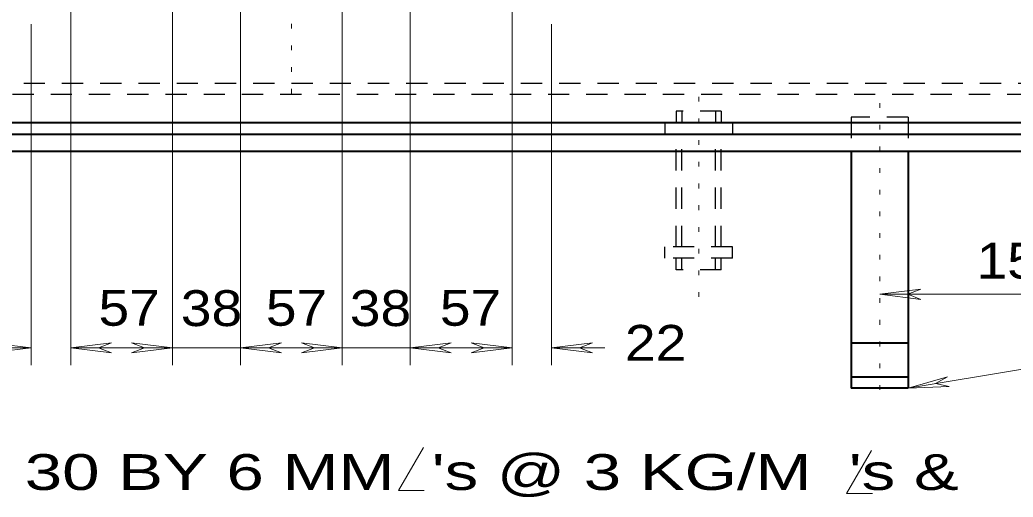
# Model space of a CAD drawing. Extents: x 312583 to 312854, y 144419 to 144597.
# Drawn here: x 312664.38 to 312685.41, y 144537.74 to 144547.86 of the extents above; entities that cross this region are included whole.
import ezdxf

# ---------------------------------------------------------------- set-up
doc = ezdxf.new("R2010")
doc.units = 0
doc.header["$LTSCALE"] = 0.3
doc.linetypes.add('DOTTED', pattern=[1.5, 0.3, -1.2])
doc.linetypes.add('SHORT_DASHED', pattern=[2.7, 1.5, -1.2])
doc.layers.add('1', color=7, linetype='Continuous', lineweight=13)

msp = doc.modelspace()

# ---------------------------------------------------------------- linework, layer by layer
at = {"layer": '1'}
for p, q in [((312665.4586, 144554.099), (312665.4586, 144540.5366)), ((312667.6129, 144554.007), (312667.6129, 144540.5366)), ((312674.8043, 144553.6926), (312674.8043, 144540.5366)), ((312669.0543, 144553.4013), (312669.0543, 144540.5366)), ((312671.2086, 144553.4013), (312671.2086, 144540.5366)), ((312672.6499, 144553.4243), (312672.6499, 144540.5366)), ((312664.6229, 144547.7663), (312664.6229, 144540.5366)), ((312675.6399, 144547.7663), (312675.6399, 144540.5366)), ((312682.5936, 144542.0393), (312683.4599, 144542.1466)), ((312688.5813, 144542.0393), (312682.5936, 144542.0393)), ((312682.5936, 144542.0393), (312683.4599, 144541.932)), ((312683.4599, 144542.1466), (312683.1839, 144542.0393)), ((312683.4599, 144541.932), (312683.1839, 144542.0393)), ((312664.6229, 144540.9046), (312663.7566, 144541.012)), ((312665.4586, 144540.9046), (312666.3249, 144541.012)), ((312666.3249, 144541.012), (312666.0489, 144540.9046)), ((312666.7466, 144541.012), (312667.0226, 144540.9046)), ((312667.6129, 144540.9046), (312666.7466, 144541.012)), ((312669.0543, 144540.9046), (312669.9206, 144541.012)), ((312669.9206, 144541.012), (312669.6446, 144540.9046)), ((312670.3423, 144541.012), (312670.6183, 144540.9046)), ((312671.2086, 144540.9046), (312670.3423, 144541.012)), ((312672.6499, 144540.9046), (312673.5163, 144541.012)), ((312673.5163, 144541.012), (312673.2403, 144540.9046)), ((312673.9379, 144541.012), (312674.2139, 144540.9046)), ((312674.8043, 144540.9046), (312673.9379, 144541.012)), ((312675.6399, 144540.9046), (312676.5063, 144541.012)), ((312676.5063, 144541.012), (312676.2303, 144540.9046)), ((312663.3809, 144540.9046), (312664.6229, 144540.9046)), ((312664.6229, 144540.9046), (312663.7566, 144540.7973)), ((312665.4586, 144540.9046), (312666.3249, 144540.7973)), ((312666.3249, 144540.7973), (312666.0489, 144540.9046)), ((312666.7466, 144540.7973), (312667.0226, 144540.9046)), ((312667.6129, 144540.9046), (312666.7466, 144540.7973)), ((312669.0543, 144540.9046), (312669.9206, 144540.7973)), ((312669.9206, 144540.7973), (312669.6446, 144540.9046)), ((312670.3423, 144540.7973), (312670.6183, 144540.9046)), ((312671.2086, 144540.9046), (312670.3423, 144540.7973)), ((312672.6499, 144540.9046), (312673.5163, 144540.7973)), ((312673.5163, 144540.7973), (312673.2403, 144540.9046)), ((312673.9379, 144540.7973), (312674.2139, 144540.9046)), ((312674.8043, 144540.9046), (312673.9379, 144540.7973)), ((312675.6399, 144540.9046), (312676.7669, 144540.9046)), ((312675.6399, 144540.9046), (312676.5063, 144540.7973)), ((312676.5063, 144540.7973), (312676.2303, 144540.9046)), ((312685.6143, 144540.4523), (312683.1916, 144540.046)), ((312683.1916, 144540.046), (312684.0273, 144540.2913)), ((312684.0273, 144540.2913), (312683.7743, 144540.1456)), ((312683.1916, 144540.046), (312684.0579, 144540.0843)), ((312684.0579, 144540.0843), (312683.7743, 144540.1456))]:
    msp.add_line(p, q, dxfattribs=at)
at = {"layer": '1', "linetype": 'DOTTED'}
for p, q in [((312670.1353, 144553.754), (312670.1353, 144546.0873)), ((312678.7603, 144541.9856), (312678.7603, 144546.4706)), ((312682.5936, 144546.095), (312682.5936, 144539.701))]:
    msp.add_line(p, q, dxfattribs=at)
at = {"layer": '1', "linetype": 'SHORT_DASHED', "lineweight": 25}
for p, q in [((312652.8853, 144546.279), (312687.3853, 144546.279)), ((312679.2356, 144545.9186), (312678.2773, 144545.9186)), ((312678.2773, 144545.9186), (312678.2773, 144545.681)), ((312678.3999, 144545.9186), (312678.3999, 144545.681)), ((312679.1129, 144545.9186), (312679.1129, 144545.681)), ((312679.2356, 144545.9186), (312679.2356, 144545.681)), ((312683.1916, 144545.796), (312681.9879, 144545.796)), ((312681.9879, 144545.796), (312681.9879, 144545.0753)), ((312683.1916, 144545.796), (312683.1916, 144545.0753)), ((312679.4733, 144545.681), (312678.0396, 144545.681)), ((312678.0396, 144545.681), (312678.0396, 144545.4356)), ((312679.4733, 144545.681), (312679.4733, 144545.4356)), ((312678.2773, 144543.0436), (312678.2773, 144545.4356)), ((312678.3999, 144543.0436), (312678.3999, 144545.4356)), ((312679.1129, 144543.0436), (312679.1129, 144545.4356)), ((312679.2356, 144543.0436), (312679.2356, 144545.4356)), ((312679.4733, 144543.0436), (312678.0396, 144543.0436)), ((312678.0396, 144542.806), (312678.0396, 144543.0436)), ((312679.4733, 144542.806), (312679.4733, 144543.0436)), ((312679.4733, 144542.806), (312678.0396, 144542.806)), ((312678.2773, 144542.5606), (312678.2773, 144542.806)), ((312678.3999, 144542.5606), (312678.3999, 144542.806)), ((312679.1129, 144542.5606), (312679.1129, 144542.806)), ((312679.2356, 144542.5606), (312679.2356, 144542.806)), ((312679.2356, 144542.5606), (312678.2773, 144542.5606))]:
    msp.add_line(p, q, dxfattribs=at)
at = {"layer": '1', "lineweight": 40}
for p, q in [((312652.2796, 144545.681), (312687.9833, 144545.681)), ((312652.0419, 144545.4356), (312688.2209, 144545.4356)), ((312651.6816, 144545.0753), (312688.5813, 144545.0753)), ((312681.9879, 144545.0753), (312681.9879, 144540.046)), ((312683.1916, 144545.0753), (312683.1916, 144540.046)), ((312683.1916, 144541.0043), (312681.9879, 144541.0043)), ((312683.1916, 144540.2836), (312681.9879, 144540.2836)), ((312683.1916, 144540.046), (312681.9879, 144540.046))]:
    msp.add_line(p, q, dxfattribs=at)
at = {"layer": '1', "linetype": 'SHORT_DASHED', "lineweight": 25}
msp.add_lwpolyline([(312653.1229, 144563.2836), (312653.1229, 144546.5166), (312687.1399, 144546.5166)], dxfattribs=at)
at = {"layer": '1'}
for points in [[(312665.4586, 144540.9046), (312667.6129, 144540.9046), (312669.0543, 144540.9046), (312671.2086, 144540.9046), (312672.6499, 144540.9046), (312674.8043, 144540.9046)], [(312672.9299, 144538.7925), (312672.4009, 144537.8802), (312672.9452, 144537.8802)], [(312682.4184, 144538.7292), (312681.8894, 144537.8169), (312682.4338, 144537.8169)]]:
    msp.add_lwpolyline(points, dxfattribs=at)

# ---------------------------------------------------------------- texts
for s, width, p in [('159 ', 1.15, (312684.6397, 144542.3709)), ('57 ', 1.15, (312666.0469, 144541.3725)), ('38 ', 1.15, (312667.7889, 144541.3656)), ('57 ', 1.15, (312669.5902, 144541.3725)), ('38 ', 1.15, (312671.3677, 144541.3656)), ('57 ', 1.15, (312673.2753, 144541.3725)), ('22 ', 1.15, (312677.194, 144540.6295)), ("30 BY 30 BY 6 MM  's @ 3 KG/M  's &", 1.4, (312660.2146, 144537.8906))]:
    msp.add_text(s, height=0.76, dxfattribs=dict(at, width=width)).set_placement(p)

doc.saveas('drawing.dxf')
